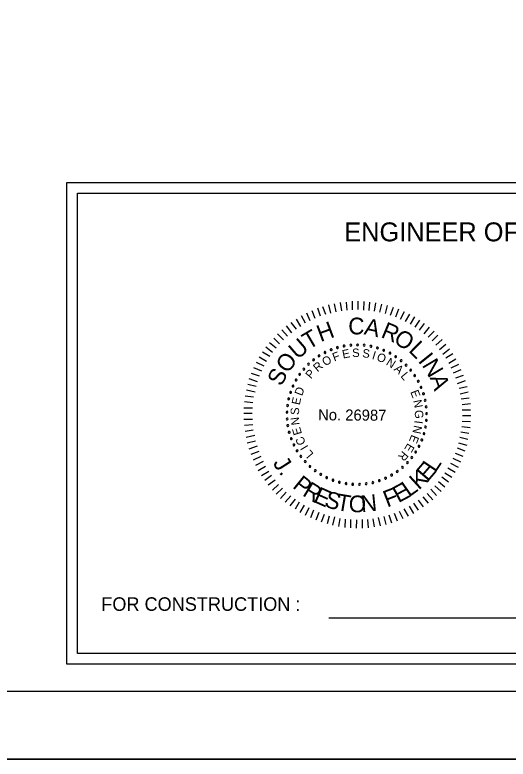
# Model space of a CAD drawing. Extents: x -1142 to 658, y -589 to 511.
# Drawn here: x 255.9 to 438.1, y -589.3 to -314.3 of the extents above; entities that cross this region are included whole.
import ezdxf

# ---------------------------------------------------------------- set-up
doc = ezdxf.new("R2010")
doc.units = 0
for name, color, linetype in [('BR_BORDER LINES', 7, 'Continuous'), ('BR_TEXT', 7, 'Continuous'), ('Default', 7, 'Continuous'), ('Level 31', 7, 'Continuous'), ('RD_SHT_IplotShp', 7, 'Continuous')]:
    doc.layers.add(name, color=color, linetype=linetype)

msp = doc.modelspace()

# ---------------------------------------------------------------- linework, layer by layer
at = {"layer": 'BR_BORDER LINES'}
msp.add_line((-1041.79, -564.26), (633.21, -564.26), dxfattribs=at)
at = {"layer": 'BR_TEXT'}
for p, q in [((376.61, -423.67), (376.16, -420.62)), ((378.58, -423.47), (378.4, -420.43)), ((380.56, -423.36), (380.59, -420.14)), ((382.66, -423.25), (382.69, -420.16)), ((384.76, -423.4), (384.88, -420.18)), ((386.78, -423.54), (387.02, -420.5)), ((388.71, -423.77), (389.25, -420.73)), ((368.78, -425.67), (367.74, -422.74)), ((370.76, -425.04), (369.67, -422.16)), ((372.57, -424.54), (371.91, -421.49)), ((374.63, -424.04), (373.93, -421.08)), ((390.72, -424.18), (391.43, -421.22)), ((392.78, -424.71), (393.58, -421.67)), ((394.62, -425.24), (395.71, -422.37)), ((396.59, -425.9), (397.68, -422.99)), ((363.27, -428.24), (361.75, -425.52)), ((364.99, -427.35), (363.69, -424.55)), ((366.85, -426.51), (365.67, -423.71)), ((398.38, -426.77), (399.78, -423.99)), ((400.18, -427.64), (401.74, -424.87)), ((402.06, -428.56), (403.67, -425.87)), ((359.95, -430.49), (357.99, -427.94)), ((361.5, -429.43), (359.98, -426.71)), ((403.72, -429.77), (405.42, -427.09)), ((405.39, -430.86), (407.21, -428.35)), ((356.62, -432.99), (354.54, -430.74)), ((358.26, -431.76), (356.27, -429.25)), ((407.01, -432.16), (409.04, -429.69)), ((408.58, -433.42), (410.74, -431.21)), ((353.68, -435.89), (351.51, -433.76)), ((355.15, -434.35), (352.94, -432.15)), ((409.99, -434.8), (412.15, -432.63)), ((411.39, -436.36), (413.77, -434.28)), ((351.12, -439.12), (348.65, -437.13)), ((352.42, -437.46), (349.95, -435.51)), ((412.75, -437.96), (415.08, -436.05)), ((350.04, -440.57), (347.35, -438.92)), ((413.94, -439.64), (416.4, -437.69)), ((415.04, -441.11), (417.67, -439.5)), ((347.95, -444.12), (345.13, -442.72)), ((348.82, -442.41), (346.13, -440.8)), ((416.14, -442.97), (418.81, -441.4)), ((347.07, -445.96), (344.21, -444.69)), ((417.03, -444.69), (419.91, -443.34)), ((417.91, -446.54), (420.76, -445.32)), ((346.2, -447.88), (343.29, -446.78)), ((418.76, -448.48), (421.6, -447.43)), ((344.97, -451.69), (341.93, -450.93)), ((345.58, -449.89), (342.5, -448.75)), ((419.43, -450.5), (422.31, -449.41)), ((344.61, -453.79), (341.48, -452.99)), ((419.93, -452.31), (422.94, -451.6)), ((420.34, -454.41), (423.35, -453.67)), ((344.08, -455.59), (341.03, -455.17)), ((420.75, -456.22), (423.72, -455.86)), ((343.85, -457.64), (340.76, -457.28)), ((421.08, -458.28), (424.13, -457.96)), ((343.6, -461.67), (340.47, -461.65)), ((343.7, -459.62), (340.48, -459.59)), ((421.15, -460.26), (424.15, -460.28)), ((343.67, -463.82), (340.45, -463.88)), ((421.11, -464.46), (424.12, -464.57)), ((421.26, -462.32), (424.3, -462.34)), ((343.78, -465.75), (340.69, -466.11)), ((421.01, -466.39), (424.05, -466.8)), ((343.98, -467.81), (340.93, -468.26)), ((344.48, -469.79), (341.34, -470.45)), ((420.65, -468.45), (423.61, -468.94)), ((344.8, -471.9), (341.75, -472.6)), ((419.76, -472.52), (422.76, -473.27)), ((420.21, -470.42), (423.2, -471.13)), ((345.39, -473.75), (342.29, -474.79)), ((345.97, -475.68), (343.05, -476.73)), ((419.23, -474.36), (422.1, -475.45)), ((346.81, -477.54), (343.93, -478.88)), ((417.65, -478.12), (420.47, -479.52)), ((418.53, -476.28), (421.35, -477.38)), ((347.66, -479.34), (344.81, -480.82)), ((348.5, -481.2), (345.79, -482.76)), ((416.74, -479.92), (419.6, -481.44)), ((349.69, -483.05), (346.97, -484.62)), ((414.69, -483.59), (417.29, -485.2)), ((415.82, -481.75), (418.47, -483.36)), ((350.75, -484.52), (348.24, -486.34)), ((352.02, -486.2), (349.52, -488.16)), ((412.35, -486.7), (414.65, -488.69)), ((413.56, -485.04), (415.99, -486.9)), ((353.25, -487.89), (351.05, -489.93)), ((354.7, -489.19), (352.45, -491.44)), ((410.96, -488.36), (413.3, -490.44)), ((356.15, -490.7), (354.02, -493)), ((357.77, -492), (355.73, -494.34)), ((408.11, -491.13), (410.23, -493.46)), ((409.53, -489.64), (411.66, -491.93)), ((359.43, -493.3), (357.44, -495.69)), ((360.96, -494.39), (359.4, -496.99)), ((403.18, -494.74), (404.84, -497.37)), ((404.87, -493.68), (406.65, -496.09)), ((406.51, -492.4), (408.5, -494.78)), ((362.71, -495.52), (361.15, -498.21)), ((364.42, -496.52), (363.07, -499.3)), ((366.26, -497.39), (365.04, -500.17)), ((397.8, -497.65), (399.15, -500.45)), ((399.61, -496.81), (401.13, -499.61)), ((401.5, -495.84), (403.07, -498.55)), ((368.18, -498.26), (367.09, -501.09)), ((370.15, -498.88), (369.01, -501.79)), ((371.95, -499.5), (371.24, -502.45)), ((374.01, -499.86), (373.25, -502.94)), ((375.97, -500.43), (375.48, -503.35)), ((390.1, -499.99), (390.76, -503.09)), ((392.16, -499.67), (392.91, -502.63)), ((394.01, -499.08), (395.06, -502.01)), ((395.99, -498.49), (397.04, -501.34)), ((377.95, -500.66), (377.71, -503.75)), ((379.92, -500.81), (379.9, -503.9)), ((382.02, -500.95), (382, -504)), ((384.13, -500.84), (384.19, -503.93)), ((386.14, -500.73), (386.33, -503.82)), ((388.07, -500.53), (388.57, -503.45))]:
    msp.add_line(p, q, dxfattribs=at)
for centre, start, end in [((375.06, -437.25), 16.1422, 196.1422), ((375.06, -437.25), 196.1422, 16.1422), ((377.49, -436.68), 10.6038, 190.6038), ((377.49, -436.68), 190.6038, 10.6038), ((379.96, -436.34), 5.0653, 185.0653), ((379.96, -436.34), 185.0653, 5.0653), ((382.45, -436.25), 359.5268, 179.5268), ((382.45, -436.25), 179.5268, 359.5268), ((384.94, -436.39), 353.9884, 173.9884), ((384.94, -436.39), 173.9884, 353.9884), ((387.4, -436.78), 348.4499, 168.4499), ((387.4, -436.78), 168.4499, 348.4499), ((389.81, -437.4), 342.9114, 162.9114), ((368.28, -440.32), 32.7576, 212.7576), ((370.44, -439.08), 27.2191, 207.2191), ((370.44, -439.08), 207.2191, 27.2191), ((372.71, -438.05), 21.6807, 201.6807), ((372.71, -438.05), 201.6807, 21.6807), ((389.81, -437.4), 162.9114, 342.9114), ((392.15, -438.25), 157.373, 337.373), ((392.15, -438.25), 337.373, 157.373), ((394.4, -439.32), 151.8345, 331.8345), ((394.4, -439.32), 331.8345, 151.8345), ((366.24, -441.76), 38.2961, 218.2961), ((366.24, -441.76), 218.2961, 38.2961), ((368.28, -440.32), 212.7576, 32.7576), ((396.54, -440.61), 146.2961, 326.2961), ((396.54, -440.61), 326.2961, 146.2961), ((398.54, -442.09), 140.7576, 320.7576), ((398.54, -442.09), 320.7576, 140.7576), ((362.65, -445.2), 49.373, 229.373), ((362.65, -445.2), 229.373, 49.373), ((364.36, -443.4), 43.8345, 223.8345), ((364.36, -443.4), 223.8345, 43.8345), ((400.38, -443.77), 135.2191, 315.2191), ((400.38, -443.77), 315.2191, 135.2191), ((402.06, -445.61), 129.6807, 309.6807), ((402.06, -445.61), 309.6807, 129.6807), ((361.11, -447.17), 54.9114, 234.9114), ((361.11, -447.17), 234.9114, 54.9114), ((403.55, -447.6), 124.1422, 304.1422), ((403.55, -447.6), 304.1422, 124.1422), ((359.78, -449.27), 60.4499, 240.4499), ((359.78, -449.27), 240.4499, 60.4499), ((404.85, -449.73), 118.6038, 298.6038), ((404.85, -449.73), 298.6038, 118.6038), ((357.74, -453.81), 71.5268, 251.5268), ((357.74, -453.81), 251.5268, 71.5268), ((358.65, -451.49), 65.9884, 245.9884), ((358.65, -451.49), 245.9884, 65.9884), ((405.93, -451.98), 113.0653, 293.0653), ((405.93, -451.98), 293.0653, 113.0653), ((357.07, -456.21), 77.0653, 257.0653), ((357.07, -456.21), 257.0653, 77.0653), ((406.79, -454.31), 107.5268, 287.5268), ((406.79, -454.31), 287.5268, 107.5268), ((407.42, -456.73), 101.9884, 281.9884), ((407.42, -456.73), 281.9884, 101.9884), ((356.62, -458.66), 82.6038, 262.6038), ((356.62, -458.66), 262.6038, 82.6038), ((407.81, -459.19), 96.4499, 276.4499), ((407.81, -459.19), 276.4499, 96.4499), ((356.41, -461.14), 88.1422, 268.1422), ((356.41, -461.14), 268.1422, 88.1422), ((407.97, -461.67), 90.9114, 270.9114), ((407.97, -461.67), 270.9114, 90.9114), ((356.45, -463.64), 93.6807, 273.6807), ((356.45, -463.64), 273.6807, 93.6807), ((407.88, -464.16), 85.373, 265.373), ((407.88, -464.16), 265.373, 85.373), ((356.72, -466.11), 99.2191, 279.2191), ((356.72, -466.11), 279.2191, 99.2191), ((407.56, -466.63), 79.8345, 259.8345), ((407.56, -466.63), 259.8345, 79.8345), ((357.24, -468.55), 104.7576, 284.7576), ((357.24, -468.55), 284.7576, 104.7576), ((406.99, -469.06), 74.2961, 254.2961), ((406.99, -469.06), 254.2961, 74.2961), ((357.98, -470.93), 110.2961, 290.2961), ((357.98, -470.93), 290.2961, 110.2961), ((358.95, -473.22), 115.8345, 295.8345), ((358.95, -473.22), 295.8345, 115.8345), ((406.2, -471.42), 68.7576, 248.7576), ((406.2, -471.42), 248.7576, 68.7576), ((360.14, -475.41), 121.373, 301.373), ((360.14, -475.41), 301.373, 121.373), ((403.95, -475.86), 57.6807, 237.6807), ((403.95, -475.86), 237.6807, 57.6807), ((405.18, -473.7), 63.2191, 243.2191), ((405.18, -473.7), 243.2191, 63.2191), ((361.54, -477.48), 126.9114, 306.9114), ((361.54, -477.48), 306.9114, 126.9114), ((402.51, -477.9), 52.1422, 232.1422), ((402.51, -477.9), 232.1422, 52.1422), ((363.12, -479.4), 132.4499, 312.4499), ((363.12, -479.4), 312.4499, 132.4499), ((364.89, -481.16), 137.9884, 317.9884), ((364.89, -481.16), 317.9884, 137.9884), ((399.08, -481.51), 41.0653, 221.0653), ((400.89, -479.78), 46.6038, 226.6038), ((400.89, -479.78), 226.6038, 46.6038), ((366.82, -482.74), 143.5268, 323.5268), ((366.82, -482.74), 323.5268, 143.5268), ((368.89, -484.12), 149.0653, 329.0653), ((368.89, -484.12), 329.0653, 149.0653), ((397.13, -483.05), 35.5268, 215.5268), ((397.13, -483.05), 215.5268, 35.5268), ((399.08, -481.51), 221.0653, 41.0653), ((371.08, -485.3), 154.6038, 334.6038), ((371.08, -485.3), 334.6038, 154.6038), ((373.38, -486.27), 160.1422, 340.1422), ((373.38, -486.27), 340.1422, 160.1422), ((375.76, -487), 345.6807, 165.6807), ((390.49, -486.44), 18.9114, 198.9114), ((390.49, -486.44), 198.9114, 18.9114), ((392.81, -485.53), 24.4499, 204.4499), ((392.81, -485.53), 204.4499, 24.4499), ((395.03, -484.39), 29.9884, 209.9884), ((395.03, -484.39), 209.9884, 29.9884), ((375.76, -487), 165.6807, 345.6807), ((378.2, -487.51), 351.2191, 171.2191), ((378.2, -487.51), 171.2191, 351.2191), ((380.67, -487.77), 356.7576, 176.7576), ((380.67, -487.77), 176.7576, 356.7576), ((383.17, -487.8), 2.2961, 182.2961), ((383.17, -487.8), 182.2961, 2.2961), ((385.65, -487.58), 7.8345, 187.8345), ((385.65, -487.58), 187.8345, 7.8345), ((388.1, -487.13), 13.373, 193.373), ((388.1, -487.13), 193.373, 13.373)]:
    msp.add_arc(centre, 0.351, start, end, dxfattribs=at)
at = {"layer": 'Default'}
msp.add_line((371.83, -537.07), (510.46, -537.07), dxfattribs=at)
for points in [[(275.07, -376.26), (593.07, -376.26), (593.07, -554.26), (275.07, -554.26)], [(279.07, -380.26), (589.07, -380.26), (589.07, -550.26), (279.07, -550.26)]]:
    msp.add_lwpolyline(points, close=True, dxfattribs=at)
at = {"layer": 'Level 31'}
msp.add_lwpolyline([(-1141.79, 510.67), (-1141.79, -589.33), (658.21, -589.33), (658.21, 510.67)], dxfattribs=at)
at = {"layer": 'RD_SHT_IplotShp'}
msp.add_line((-1141.79, -589.26), (658.21, -589.26), dxfattribs=at)

# ---------------------------------------------------------------- texts
at = {"layer": 'BR_TEXT'}
for s, height, rotation, p in [('C', 6.2, 359.5482, (379.02, -432.37)), ('H', 6.2, 20.3637, (368.8, -435.28)), ('A', 6.2, 348.1981, (384.6, -432.33)), ('R', 6.2, 337.4344, (390.76, -433.32)), ('T', 6.2, 30.4992, (364.41, -438.16)), ('O', 6.2, 326.5869, (395.37, -435.16)), ('U', 6.2, 40.8022, (360.35, -441.9)), ('L', 6.2, 315.9488, (401, -438.55)), ('O', 6.2, 52.0267, (356.62, -447.09)), ('F', 3.11, 20.6127, (373.87, -442.43)), ('E', 3.11, 11.4103, (377.13, -441.34)), ('S', 3.11, 2.208, (380.52, -440.79)), ('S', 3.11, 352.6608, (384.08, -440.8)), ('I', 3.11, 343.1136, (387.59, -441.41)), ('O', 3.11, 338.4392, (389.26, -441.91)), ('I', 6.2, 308.6613, (404.57, -442.26)), ('R', 3.11, 40.3949, (367.69, -446.42)), ('O', 3.11, 30.8477, (370.5, -444.23)), ('N', 3.11, 328.2042, (392.74, -443.48)), ('N', 6.2, 300.7037, (406.1, -443.73)), ('S', 6.2, 63.2511, (354.35, -451.87)), ('P', 3.11, 49.9421, (365.29, -449.05)), ('A', 3.11, 318.657, (395.69, -445.48)), ('L', 3.11, 309.4546, (398.18, -447.85)), ('A', 6.2, 289.4792, (409.06, -448.38)), ('D', 3.11, 69.0364, (361.94, -455.32)), ('E', 3.11, 291.049, (401.88, -453.62)), ('E', 3.11, 78.2388, (361.11, -458.65)), ('N', 3.11, 281.8466, (402.99, -456.87)), ('S', 3.11, 87.786, (360.83, -462.2)), ('No. 26987', 4.087, 359.5268, (367.88, -464.12)), ('G', 3.11, 272.2995, (403.57, -460.38)), ('N', 3.11, 97.3332, (361.13, -465.75)), ('I', 3.11, 262.4084, (403.56, -464.07)), ('E', 3.11, 106.5355, (361.98, -469.08)), ('N', 3.11, 257.7339, (403.33, -465.8)), ('C', 3.11, 116.4266, (363.48, -472.46)), ('E', 3.11, 248.1867, (402.43, -469.25)), ('E', 3.11, 238.9844, (401.03, -472.39)), ('I', 3.11, 121.1011, (364.38, -473.95)), ('L', 3.11, 129.9595, (366.41, -476.56)), ('R', 3.11, 229.782, (399.15, -475.26)), ('J', 6.18, 302.9559, (351.02, -479.98)), ('E', 6.18, 49.3639, (408.32, -487.07)), ('L', 6.18, 56.4247, (411.19, -483.69)), ('.', 6.18, 309.3974, (353.22, -483.38)), ('K', 6.18, 42.3031, (405.05, -490.08)), ('P', 6.18, 321.1035, (358.15, -488.84)), ('R', 6.18, 328.5359, (361.81, -491.74)), ('E', 6.18, 335.9684, (365.82, -494.15)), ('F', 6.18, 21.1206, (393.4, -496.4)), ('E', 6.18, 28.1814, (397.54, -494.78)), ('L', 6.18, 35.2422, (401.44, -492.66)), ('S', 6.18, 343.0292, (369.88, -495.93)), ('T', 6.18, 350.4617, (374.36, -497.26)), ('O', 6.18, 358.1419, (379.13, -498.01)), ('N', 6.18, 5.8221, (383.96, -498.11))]:
    msp.add_text(s, height=height, rotation=rotation, dxfattribs=at).set_placement(p)
at = {"layer": 'Default'}
for s, height, p in [('ENGINEER OF RECORD', 7, (377.57, -398.01)), ('FOR CONSTRUCTION :', 5.0001, (287.84, -534.54))]:
    msp.add_text(s, height=height, dxfattribs=at).set_placement(p)

doc.saveas('drawing.dxf')
